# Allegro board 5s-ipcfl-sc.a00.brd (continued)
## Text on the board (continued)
Ref Des/Silkscreen Top: JUMPER | P216 | P215 | P217 | MODE FUNCTION | SERVICE_MODE | PASSWORD CLR | CMOS CLR | 1+2PIN:DISABLE | 2+3PIN:DEFAULT | OPEN:DEFAULT | SHORT:DEFAULT | OPEN:CLEAR | SHORT:CLEAR | OPERATION | Label | (0.00,0.00) | 2230 | PCIE X8 | PCIE X4 | REV:A00 | F2 | 3 1 4 2 | DDR4 | 2260 | 2242 | 2280 | (9600.00,9600.00) | PCB MADE IN CHINA
VCC: list("[Spacing] VCC" "16.Thru Pin to Thru Pin" "5 MIL [DEFAULT]" "OVERLAP" "" "DRC ERROR CLASS/VCC" "[ThruPin] Dummy (<uTiL>cId1011<uTiL>.3) (3462.78 4855.87)" "[ThruPin] Dummy (<uTiL>cId5049<uTiL>.4) (3462.79 4855.87)" list(3462.780000 4776.370000) nil)@@@list("amy_chou" "2017/07/21 16:04:56" nil "P143000034-PC" "5s-ipcfl-sc.a00")@@@list("iris_chen" "2017/07/24 16:06:30" nil "p16c000357-pc" "5s-ipcfl-sc.a00") | list("[Spacing] VCC" "15.Thru Pin to Thru Pin" "5 MIL [DEFAULT]" "OVERLAP" "" "DRC ERROR CLASS/VCC" "[ThruPin] Dummy (<uTiL>cId1011<uTiL>.2) (3462.78 7808.63)" "[ThruPin] Dummy (<uTiL>cId5049<uTiL>.5) (3462.79 7809.02)" list(3542.260000 7806.790000) nil)@@@list("amy_chou" "2017/07/21 16:04:57" nil "P143000034-PC" "5s-ipcfl-sc.a00")@@@list("iris_chen" "2017/07/24 16:06:28" nil "p16c000357-pc" "5s-ipcfl-sc.a00") | list("[Spacing] VCC" "11.Thru Pin to Thru Pin" "5 MIL [DEFAULT]" "OVERLAP" "" "DRC ERROR CLASS/VCC" "[ThruPin] Dummy (<uTiL>cId1011<uTiL>.7) (4230.5 7372.21)" "[ThruPin] Dummy (<uTiL>cId5049<uTiL>.2) (4230.51 7372.8)" list(4305.490000 7371.230000) nil)@@@list("amy_chou" "2017/07/21 16:04:57" nil "P143000034-PC" "5s-ipcfl-sc.a00")@@@list("iris_chen" "2017/07/24 16:02:13" nil "p16c000357-pc" "5s-ipcfl-sc.a00") | list("[Spacing] VCC" "13.Thru Pin to Thru Pin" "5 MIL [DEFAULT]" "OVERLAP" "" "DRC ERROR CLASS/VCC" "[ThruPin] Dummy (<uTiL>cId1011<uTiL>.5) (4939.17 4970.44)" "[ThruPin] Dummy (<uTiL>cId5049<uTiL>.1) (4939.17 4970.44)" list(5014.170000 4970.440000) nil)@@@list("amy_chou" "2017/07/21 16:04:55" nil "P143000034-PC" "5s-ipcfl-sc.a00")@@@list("iris_chen" "2017/07/24 16:06:13" nil "p16c000357-pc" "5s-ipcfl-sc.a00") | list("[Spacing] VCC" "9.Thru Pin to Thru Pin" "5 MIL [DEFAULT]" "OVERLAP" "" "DRC ERROR CLASS/VCC" "[ThruPin] Dummy (<uTiL>cId1011<uTiL>.6) (5647.83 7372.21)" "[ThruPin] Dummy (<uTiL>cId5049<uTiL>.3) (5647.83 7372.8)" list(5722.830000 7372.500000) nil)@@@list("amy_chou" "2017/07/21 16:04:57" nil "P143000034-PC" "5s-ipcfl-sc.a00")@@@list("iris_chen" "2017/07/24 16:02:10" nil "p16c000357-pc" "5s-ipcfl-sc.a00") | list("[Spacing] VCC" "14.Thru Pin to Thru Pin" "5 MIL [DEFAULT]" "OVERLAP" "" "DRC ERROR CLASS/VCC" "[ThruPin] Dummy (<uTiL>cId1011<uTiL>.1) (6415.55 7808.63)" "[ThruPin] Dummy (<uTiL>cId5049<uTiL>.7) (6415.55 7809.02)" list(6495.050000 7808.820000) nil)@@@list("amy_chou" "2017/07/21 16:04:55" nil "P143000034-PC" "5s-ipcfl-sc.a00")@@@list("iris_chen" "2017/07/24 16:06:24" nil "p16c000357-pc" "5s-ipcfl-sc.a00") | list("[Spacing] VCC" "10.Thru Pin to Thru Pin" "5 MIL [DEFAULT]" "OVERLAP" "" "DRC ERROR CLASS/VCC" "[ThruPin] Dummy (<uTiL>cId1011<uTiL>.4) (6415.55 4855.87)" "[ThruPin] Dummy (<uTiL>cId5049<uTiL>.6) (6415.55 4855.87)" list(6495.050000 4855.870000) nil)@@@list("amy_chou" "2017/07/21 16:04:58" nil "P143000034-PC" "5s-ipcfl-sc.a00")@@@list("iris_chen" "2017/07/24 16:02:11" nil "p16c000357-pc" "5s-ipcfl-sc.a00") | list("[Spacing] VCC" "12.Shape to Shape" "20 MIL [(20)]" "10 MIL" "10.00 MIL" "DRC ERROR CLASS/VCC" "[Vcc Shape] +1VSB_SW_C ((7615.0 3242.0) (8175.0 3510.0))" "[Vcc Shape] +3P3V ((1590.0 55.0) (9485.0 6230.0))" list(8175.000000 3510.000000) nil)@@@list("amy_chou" "2017/07/21 16:04:56" nil "P143000034-PC" "5s-ipcfl-sc.a00")@@@list("iris_chen" "2017/07/24 16:07:27" nil "p16c000357-pc" "5s-ipcfl-sc.a00")
IN1: list("[Spacing] IN1" "24.Drill Hole to Drill Hole" "5 MIL [DEFAULT]" "OVERLAP" "" "DRC ERROR CLASS/IN1" "[ThruPin] Dummy (<uTiL>cId1011<uTiL>.3) (3462.78 4855.87)" "[ThruPin] Dummy (<uTiL>cId5049<uTiL>.4) (3462.79 4855.87)" list(3462.780000 4776.370000) nil)@@@list("amy_chou" "2017/07/21 16:05:04" nil "P143000034-PC" "5s-ipcfl-sc.a00")@@@list("iris_chen" "2017/07/24 16:07:49" nil "p16c000357-pc" "5s-ipcfl-sc.a00") | list("[Spacing] IN1" "23.Drill Hole to Drill Hole" "5 MIL [DEFAULT]" "OVERLAP" "" "DRC ERROR CLASS/IN1" "[ThruPin] Dummy (<uTiL>cId1011<uTiL>.2) (3462.78 7808.63)" "[ThruPin] Dummy (<uTiL>cId5049<uTiL>.5) (3462.79 7809.02)" list(3542.260000 7806.790000) nil)@@@list("amy_chou" "2017/07/21 16:05:05" nil "P143000034-PC" "5s-ipcfl-sc.a00")@@@list("iris_chen" "2017/07/24 16:07:48" nil "p16c000357-pc" "5s-ipcfl-sc.a00") | list("[Spacing] IN1" "20.Drill Hole to Drill Hole" "5 MIL [DEFAULT]" "OVERLAP" "" "DRC ERROR CLASS/IN1" "[ThruPin] Dummy (<uTiL>cId1011<uTiL>.7) (4230.5 7372.21)" "[ThruPin] Dummy (<uTiL>cId5049<uTiL>.2) (4230.51 7372.8)" list(4305.490000 7371.230000) nil)@@@list("amy_chou" "2017/07/21 16:05:04" nil "P143000034-PC" "5s-ipcfl-sc.a00")@@@list("iris_chen" "2017/07/24 16:07:44" nil "p16c000357-pc" "5s-ipcfl-sc.a00") | list("[Spacing] IN1" "21.Drill Hole to Drill Hole" "5 MIL [DEFAULT]" "OVERLAP" "" "DRC ERROR CLASS/IN1" "[ThruPin] Dummy (<uTiL>cId1011<uTiL>.5) (4939.17 4970.44)" "[ThruPin] Dummy (<uTiL>cId5049<uTiL>.1) (4939.17 4970.44)" list(5014.170000 4970.440000) nil)@@@list("amy_chou" "2017/07/21 16:05:03" nil "P143000034-PC" "5s-ipcfl-sc.a00")@@@list("iris_chen" "2017/07/24 16:07:45" nil "p16c000357-pc" "5s-ipcfl-sc.a00") | list("[Spacing-SameNet] IN1" "43.Thru Pin to Thru Pin Same Net" "5 MIL [DEFAULT]" "OVERLAP" "" "DRC ERROR CLASS/IN1" "[ThruPin] GND (<uTiL>cId4700<uTiL>.2) (5645.08 2715.08)" "[ThruPin] GND (<uTiL>cId90<uTiL>.1) (5645.08 2715.08)" list(5676.080000 2715.080000) nil)@@@list("amy_chou" "2017/07/21 16:07:03" nil "P143000034-PC" "5s-ipcfl-sc.a00")@@@list("iris_chen" "2017/07/24 16:08:33" nil "p16c000357-pc" "5s-ipcfl-sc.a00") | list("[Spacing] IN1" "18.Drill Hole to Drill Hole" "5 MIL [DEFAULT]" "OVERLAP" "" "DRC ERROR CLASS/IN1" "[ThruPin] Dummy (<uTiL>cId1011<uTiL>.6) (5647.83 7372.21)" "[ThruPin] Dummy (<uTiL>cId5049<uTiL>.3) (5647.83 7372.8)" list(5722.830000 7372.500000) nil)@@@list("amy_chou" "2017/07/21 16:05:05" nil "P143000034-PC" "5s-ipcfl-sc.a00")@@@list("iris_chen" "2017/07/24 16:07:41" nil "p16c000357-pc" "5s-ipcfl-sc.a00") | list("[Spacing-SameNet] IN1" "41.Thru Pin to Thru Pin Same Net" "5 MIL [DEFAULT]" "OVERLAP" "" "DRC ERROR CLASS/IN1" "[ThruPin] GND (<uTiL>cId4700<uTiL>.1) (5845.08 2715.08)" "[ThruPin] GND (<uTiL>cId90<uTiL>.2) (5845.08 2715.08)" list(5876.080000 2715.080000) nil)@@@list("amy_chou" "2017/07/21 16:05:48" nil "P143000034-PC" "5s-ipcfl-sc.a00")@@@list("iris_chen" "2017/07/24 16:08:31" nil "p16c000357-pc" "5s-ipcfl-sc.a00") | list("[Spacing] IN1" "22.Drill Hole to Drill Hole" "5 MIL [DEFAULT]" "OVERLAP" "" "DRC ERROR CLASS/IN1" "[ThruPin] Dummy (<uTiL>cId1011<uTiL>.1) (6415.55 7808.63)" "[ThruPin] Dummy (<uTiL>cId5049<uTiL>.7) (6415.55 7809.02)" list(6495.050000 7808.820000) nil)@@@list("amy_chou" "2017/07/21 16:05:03" nil "P143000034-PC" "5s-ipcfl-sc.a00")@@@list("iris_chen" "2017/07/24 16:07:47" nil "p16c000357-pc" "5s-ipcfl-sc.a00") | list("[Spacing] IN1" "19.Drill Hole to Drill Hole" "5 MIL [DEFAULT]" "OVERLAP" "" "DRC ERROR CLASS/IN1" "[ThruPin] Dummy (<uTiL>cId1011<uTiL>.4) (6415.55 4855.87)" "[ThruPin] Dummy (<uTiL>cId5049<uTiL>.6) (6415.55 4855.87)" list(6495.050000 4855.870000) nil)@@@list("amy_chou" "2017/07/21 16:05:06" nil "P143000034-PC" "5s-ipcfl-sc.a00")@@@list("iris_chen" "2017/07/24 16:07:42" nil "p16c000357-pc" "5s-ipcfl-sc.a00") | list("[Spacing] IN1" "17.Shape to Route Keepout" "0 MIL [DEFAULT]" "0 MIL" "0.00 MIL" "DRC ERROR CLASS/IN1" "[Shape] Route Keepout/In1 ((6370.0 3020.0) (6630.0 3280.0))" "[In1 Shape] GND ((20.01 20.01) (9579.99 9579.99))" list(6630.000000 3150.000000) nil)@@@list("amy_chou" "2017/07/21 16:05:02" nil "P143000034-PC" "5s-ipcfl-sc.a00")@@@list("iris_chen" "2017/07/24 16:06:33" nil "p16c000357-pc" "5s-ipcfl-sc.a00") | list("[Spacing-SameNet] IN1" "42.Thru Pin to Thru Pin Same Net" "5 MIL [DEFAULT]" "OVERLAP" "" "DRC ERROR CLASS/IN1" "[ThruPin] GND (<uTiL>cId4701<uTiL>.2) (7604.92 1274.92)" "[ThruPin] GND (<uTiL>cId90<uTiL>.3) (7604.92 1274.92)" list(7635.920000 1274.920000) nil)@@@list("amy_chou" "2017/07/21 16:07:02" nil "P143000034-PC" "5s-ipcfl-sc.a00")@@@list("iris_chen" "2017/07/24 16:08:32" nil "p16c000357-pc" "5s-ipcfl-sc.a00") | list("[Spacing-SameNet] IN1" "40.Thru Pin to Thru Pin Same Net" "5 MIL [DEFAULT]" "OVERLAP" "" "DRC ERROR CLASS/IN1" "[ThruPin] GND (<uTiL>cId4701<uTiL>.1) (7804.92 1274.92)" "[ThruPin] GND (<uTiL>cId90<uTiL>.4) (7804.92 1274.92)" list(7835.920000 1274.920000) nil)@@@list("amy_chou" "2017/07/21 16:05:48" nil "P143000034-PC" "5s-ipcfl-sc.a00")@@@list("iris_chen" "2017/07/24 16:08:30" nil "p16c000357-pc" "5s-ipcfl-sc.a00")
NOTE: 1A | 2A | 4A | +3p3vsb  135mils | +1p05V_SA | CPU XDP | VGT | HDMI | USB 2.0 | RJ45 + USB 2.0 | DVI | USB 3.0 | AUDIO JACK | VCORE | +1P2V_DUAL/VTT
User.6: H<6.35mm | 0.20" | CONNECTOR I/O AREA | AREA A Required | Chassis 3.0" | CARD SLOT AREA, | AREA B | AREA C | 2.80" | 0.60" | 1.50"
User.7: 0.20" | H=11MM | CARD SLOT AREA, | AREA B | AREA A Required | Chassis 3.0" | AREA C | 0.60" | 2.80" | 1.50"
User.13: H<6.35mm | 0.20" | CONNECTOR I/O AREA | AREA A Required | Chassis 3.0" | CARD SLOT AREA, | AREA B | AREA C | 2.80" | 0.60" | 1.50"
User.33: +1vsb_sw_c | +5v_charger_1 | gnd | +1p05_sa_lx_d | AGND | +12v_GFX | +12V_CPU | vrm_pwm3_sw_c | vrm_pwm4_sw_c | vrm_pwm1_sw_c | vrm_pwm2_sw_c | +vcore | +VCCGT | vgt_pwm1_sw_c | vgt_pwm2_sw_c | +1VSB | GND | +1P2V_DUAL | +5v | +vcc_usb2 | +1p05v_sa | +3P3V | +5V_DUAL
User.37: 36 | 24 | 1 | 12 | 96 | 32 | 64 | A1 | B1 | A2 | B2 | A32 | B32 | 28 | 15 | B81 | A81 | A82 | B82 | 43 | 16 | 8 | 48 | 20 | 10 | 30 | 5 | 13 | 9 | R | E210882
